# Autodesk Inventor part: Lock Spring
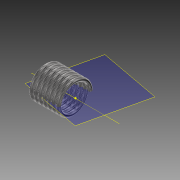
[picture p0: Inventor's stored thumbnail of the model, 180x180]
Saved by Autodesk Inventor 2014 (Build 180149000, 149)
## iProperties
Created: 2009-03
Part Number: Lock Spring
Document SubType Name: Modeling
Designer: tangg
Density: 7.84 g/cm^3
Material: Steel, High Strength Low Alloy
Mass: 2.03542 g
Surface Area: 8.33252 cm^2
Volume: 0.25962 cm^3
Appearance: Steel - Polished
Author: tangg
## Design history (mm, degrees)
sketch "Sketch1"
  geometry: 1 further point
sketch "3D Sketch1"
  node "Helical Curve1" dims "d0" = 10.238, "d1" = 70, "d2" = 9.609, "d3" = 0
workplane "Work Plane1"
sketch "Sketch2"
  geometry: C1 r 0.625 at (0, 0); 1 further point
  constraints: 1 centre point
  dimensions: "d5" = 1.25 diameter of C1
sweep "Sweep1" sketch "Sketch2" dims "d4" = 0
body "Solid1"
